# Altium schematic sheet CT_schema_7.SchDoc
size 350 x 348 mm
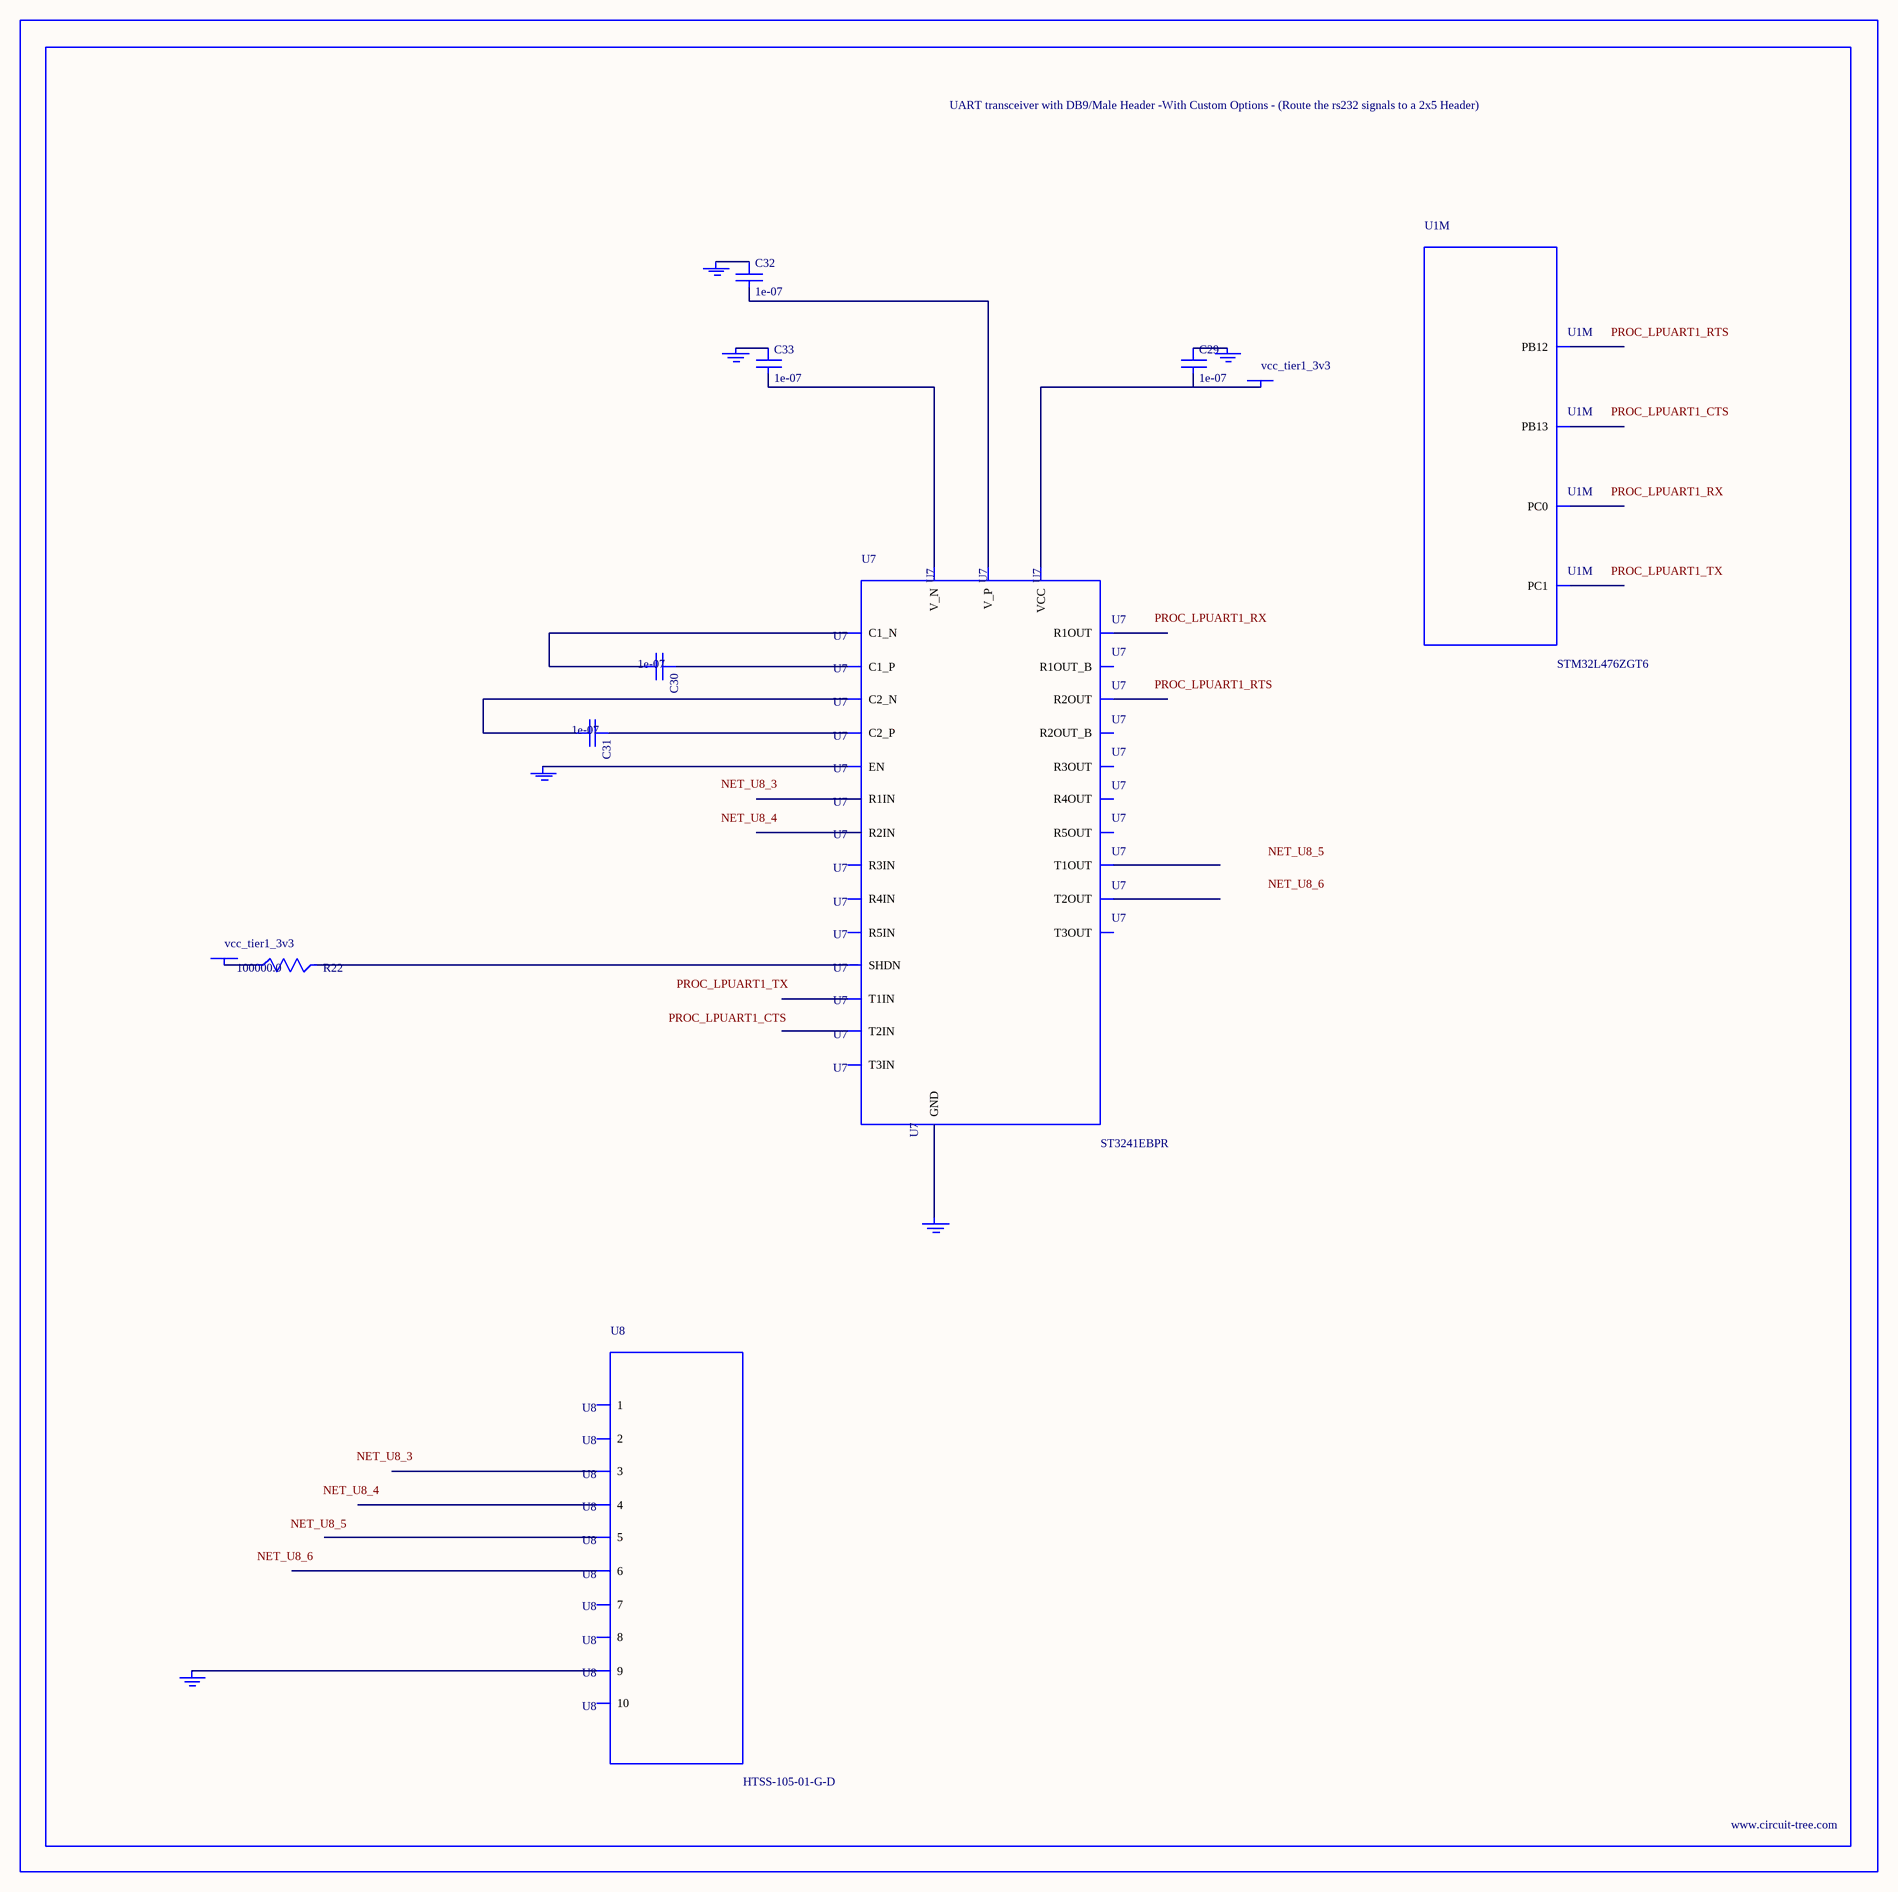
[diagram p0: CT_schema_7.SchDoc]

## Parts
BORDER6  (no value)
C29  1e-07  [C0402]
C30  1e-07  [C0402]
C31  1e-07  [C0402]
C32  1e-07  [C0402]
C33  1e-07  [C0402]
GND_INSTANCE_6_0  (no value)
GND_INSTANCE_6_1  (no value)
GND_INSTANCE_6_2  (no value)
GND_INSTANCE_6_3  (no value)
GND_INSTANCE_6_4  (no value)
GND_INSTANCE_6_5  (no value)
POWER_INSTANCE_6_0  vcc_tier1_3v3
POWER_INSTANCE_6_1  vcc_tier1_3v3
R22  100000.0  [R0603]
U1  STM32L476ZGT6  [LQFP144]  (part M of 13)
U7  ST3241EBPR  [SSOP-28]
U8  HTSS-105-01-G-D  [HTSS-105-01-G-D]

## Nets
NetC29_1: C29.1 GND_INSTANCE_6_2.0(GND)
NetC29_2: C29.2 POWER_INSTANCE_6_1.0(PWR) U7.26(VCC)
NetC30_1: C30.1 U7.28(C1_P)
NetC30_2: C30.2 U7.24(C1_N)
NetC31_1: C31.1 U7.1(C2_P)
NetC31_2: C31.2 U7.2(C2_N)
NetC32_1: C32.1 GND_INSTANCE_6_3.0(GND)
NetC32_2: C32.2 U7.27(V_P)
NetC33_1: C33.1 GND_INSTANCE_6_0.0(GND)
NetC33_2: C33.2 U7.3(V_N)
NetGND_INSTANCE_6_1_0: GND_INSTANCE_6_1.0(GND) U7.23(EN)
NetGND_INSTANCE_6_4_0: GND_INSTANCE_6_4.0(GND) U7.25(GND)
NetGND_INSTANCE_6_5_0: GND_INSTANCE_6_5.0(GND) U8.9
NetPOWER_INSTANCE_6_0_0: POWER_INSTANCE_6_0.0(PWR) R22.1
NetR22_2: R22.2 U7.22(SHDN)

Not connected (* = marked no-connect by the designer): U1 26(PC0) 27(PC1) 73(PB12) 74(PB13); U7 4(R1IN) 5(R2IN) 6(R3IN) 7(R4IN) 8(R5IN) 9(T1OUT) 10(T2OUT) 11(T3OUT) 12(T3IN) 13(T2IN) 14(T1IN) 15(R5OUT) 16(R4OUT) 17(R3OUT) 18(R2OUT) 19(R1OUT) 20(R2OUT_B) 21(R1OUT_B); U8 1 2 3 4 5 6 7 8 10

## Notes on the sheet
- Labels drawn without touching a wire or pin: NET_U8_3, NET_U8_4, NET_U8_5, NET_U8_6, PROC_LPUART1_CTS, PROC_LPUART1_RTS, PROC_LPUART1_RX, PROC_LPUART1_TX

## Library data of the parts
BORDER6 = BORDER_PAGE6
C29-C33 = C0402C104K3RACTU
GND_INSTANCE_6_0-GND_INSTANCE_6_5 = GND
POWER_INSTANCE_6_0 POWER_INSTANCE_6_1 = PWR
R22 = RC0603JR-07100KL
